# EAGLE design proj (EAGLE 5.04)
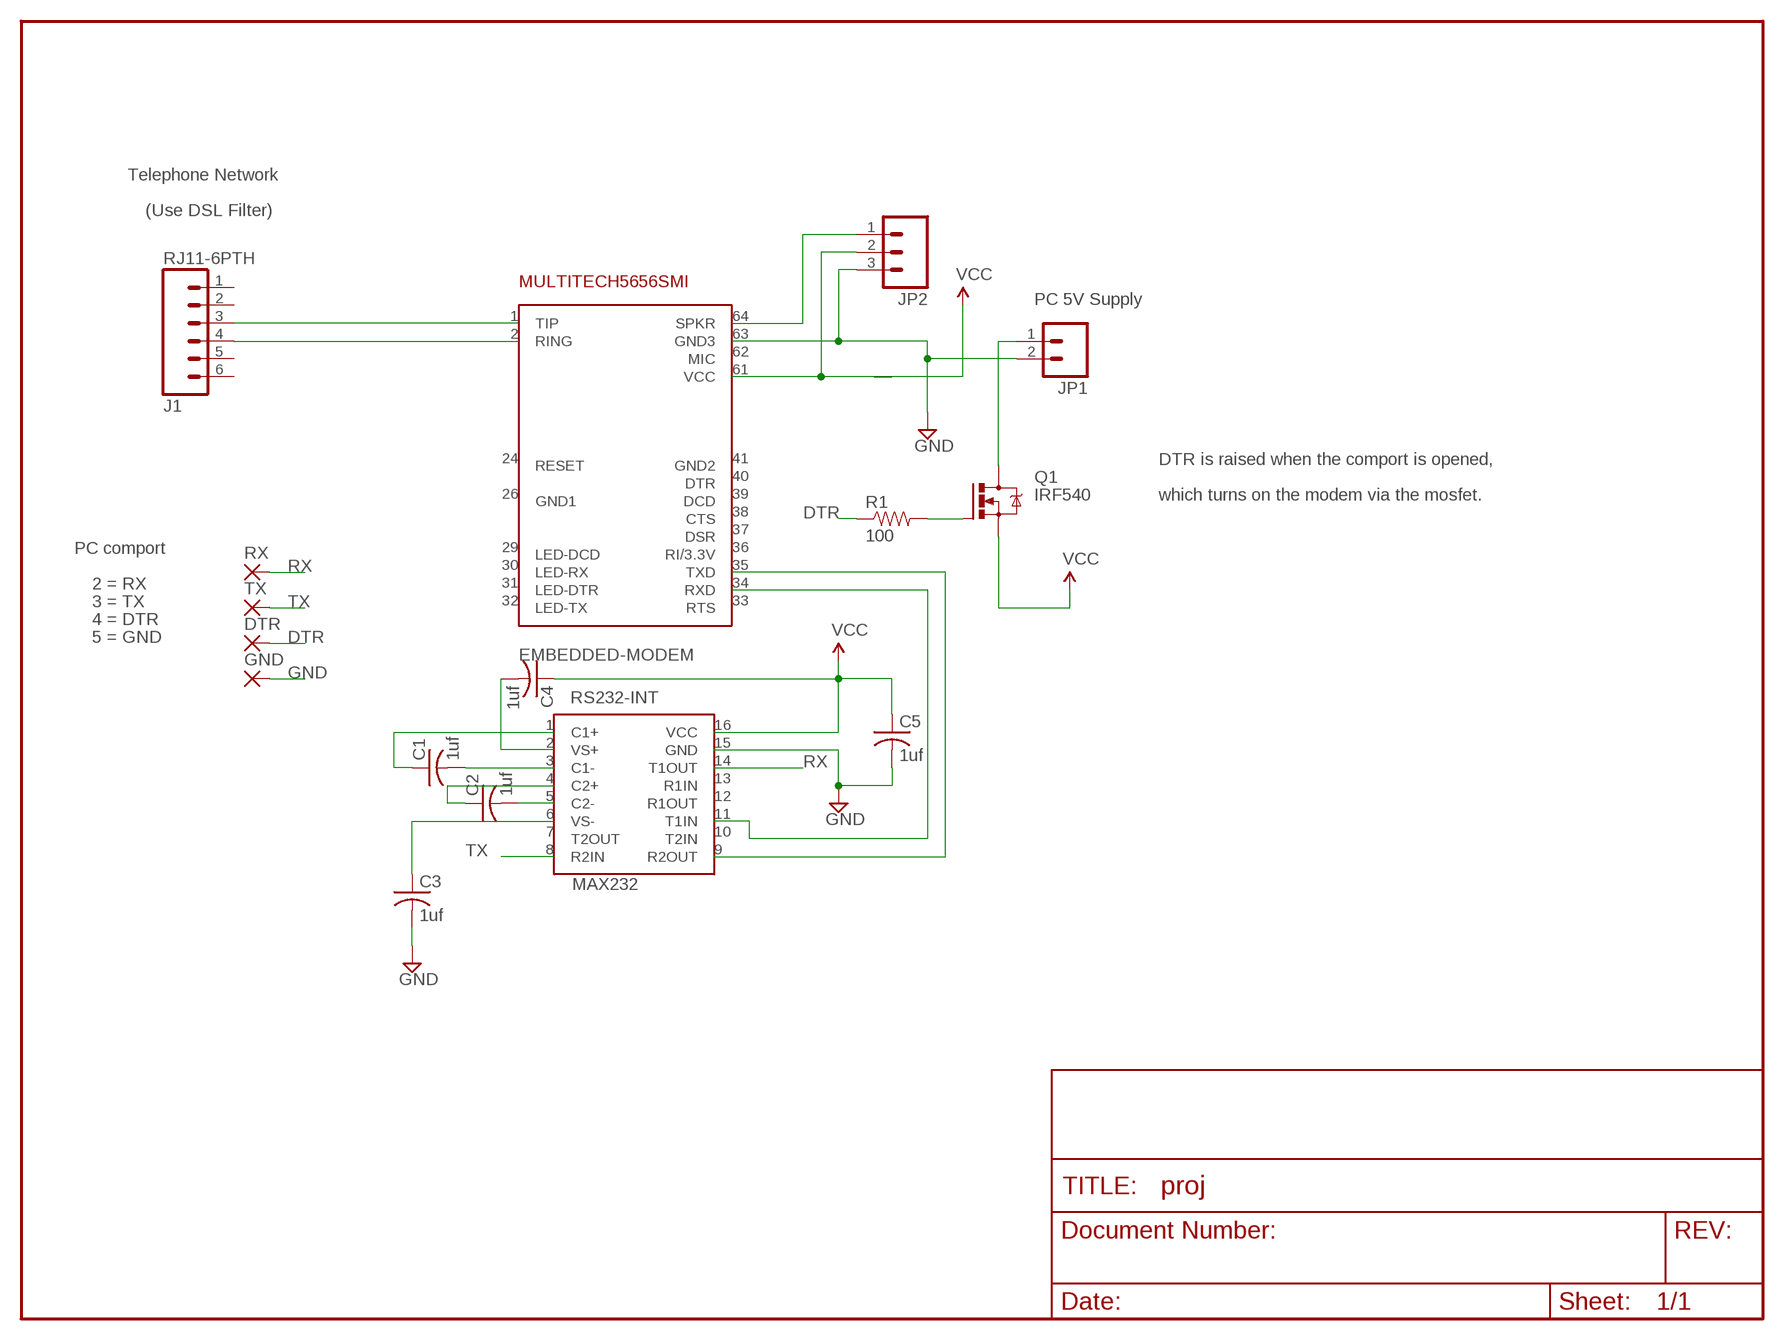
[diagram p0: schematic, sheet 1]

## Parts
C1  1uf  C-US050-024X044  [C050-024X044]
C2  1uf  C-US050-024X044  [C050-024X044]
C3  1uf  C-US050-024X044  [C050-024X044]
C4  1uf  C-US050-024X044  [C050-024X044]
C5  1uf  C-US050-024X044  [C050-024X044]
DTR  2,54/0,8  [2,54/0,8]
EMBEDDED-MODEM  MULTITECH5656SMI  [MULTITECH5656SMI]
GND  2,54/0,8  [2,54/0,8]
J1  RJ11-6PTH  [RJ11-6]
JP1  M02LOCK_LONGPADS  [1X02_LOCK_LONGPADS]
JP2  M03LOCK_LONGPADS  [1X03_LOCK_LONGPADS]
Q1  IRF540  [TO220BV]
R1  100  RESISTORPTH1  [AXIAL-0.3]
RS232-INT  MAX232  [DIL16-3]
RX  2,54/0,8  [2,54/0,8]
TX  2,54/0,8  [2,54/0,8]

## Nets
DTR: DTR.1(P) R1.P$1
GND: C3.2 C5.2 EMBEDDED-MODEM.63(GND3) GND.1(P) JP1.2 JP2.3 RS232-INT.15(GND)
N$2: Q1.G R1.P$2
N$3: JP1.1 Q1.D
N$4: EMBEDDED-MODEM.35(TXD) RS232-INT.9(R2OUT)
N$5: EMBEDDED-MODEM.34(RXD) RS232-INT.11(T1IN)
N$6: C1.2 RS232-INT.3(C1-)
N$7: C1.1 RS232-INT.1(C1+)
N$8: C2.2 RS232-INT.5(C2-)
N$9: C2.1 RS232-INT.4(C2+)
N$10: C3.1 RS232-INT.6(VS-)
N$11: C4.2 RS232-INT.2(VS+)
N$13: EMBEDDED-MODEM.64(SPKR) JP2.1
RING: EMBEDDED-MODEM.2(RING) J1.4
RX: RS232-INT.14(T1OUT) RX.1(P)
TIP: EMBEDDED-MODEM.1(TIP) J1.3
TX: RS232-INT.8(R2IN) TX.1(P)
VCC: C4.1 C5.1 EMBEDDED-MODEM.61(VCC) JP2.2 Q1.S RS232-INT.16(VCC)
Unconnected: EMBEDDED-MODEM.24(RESET) EMBEDDED-MODEM.26(GND1) EMBEDDED-MODEM.29(LED-DCD) EMBEDDED-MODEM.30(LED-RX) EMBEDDED-MODEM.31(LED-DTR) EMBEDDED-MODEM.32(LED-TX) EMBEDDED-MODEM.33(RTS) EMBEDDED-MODEM.36(RI/3.3V) EMBEDDED-MODEM.37(DSR) EMBEDDED-MODEM.38(CTS) EMBEDDED-MODEM.39(DCD) EMBEDDED-MODEM.40(DTR) EMBEDDED-MODEM.41(GND2) EMBEDDED-MODEM.62(MIC) J1.1 J1.2 J1.5 J1.6 RS232-INT.7(T2OUT) RS232-INT.10(T2IN) RS232-INT.12(R1OUT) RS232-INT.13(R1IN)

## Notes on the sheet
- Telephone Network
- (Use DSL Filter)
- PC 5V Supply
- DTR is raised when the comport is opened,
- which turns on the modem via the mosfet.
- PC comport
- 2 = RX
- 3 = TX
- 4 = DTR
- 5 = GND

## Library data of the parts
C1-C5 = rcl:C-US: CAPACITOR, American symbol
DTR GND RX TX = wirepad:2,54/0,8: THROUGH-HOLE PAD
EMBEDDED-MODEM = trl:MULTITECH5656SMI
J1 = SparkFun:RJ11-6: RJ11 Jack Simple 6 pin RJ11 jack. Commonly found on CAT3 devices and Microchip programmers. SKU: PRT-00132
JP1 = SparkFun:M02: Header 2
JP2 = SparkFun:M03: Header 3 Standard 3-pin 0.1" header. Use with straight break away headers (SKU : PRT-00116), right angle break away headers (PRT-00553), swiss pins (PRT-00743), machine pins (PRT-00117), and female headers (PRT-00115). Molex polarized connector foot print use with SKU : PRT-08232 with associated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
Q1 = transistor-power:IRF540: HEXFET Power MOSFET
R1 = SparkFun:RESISTOR: Resistor
RS232-INT = trl:MAX232

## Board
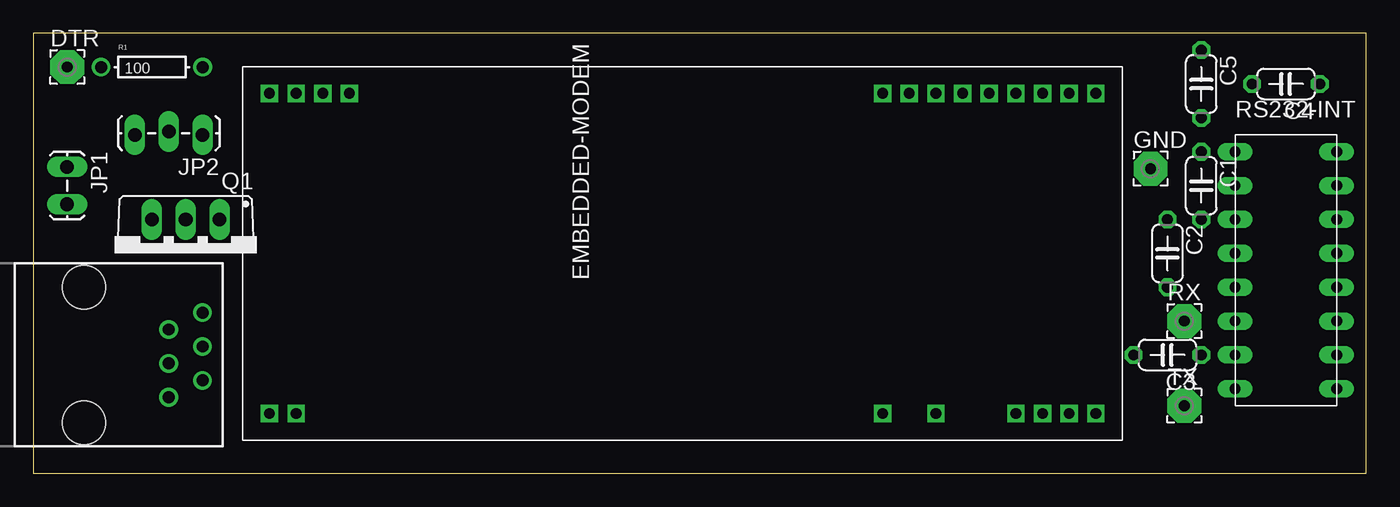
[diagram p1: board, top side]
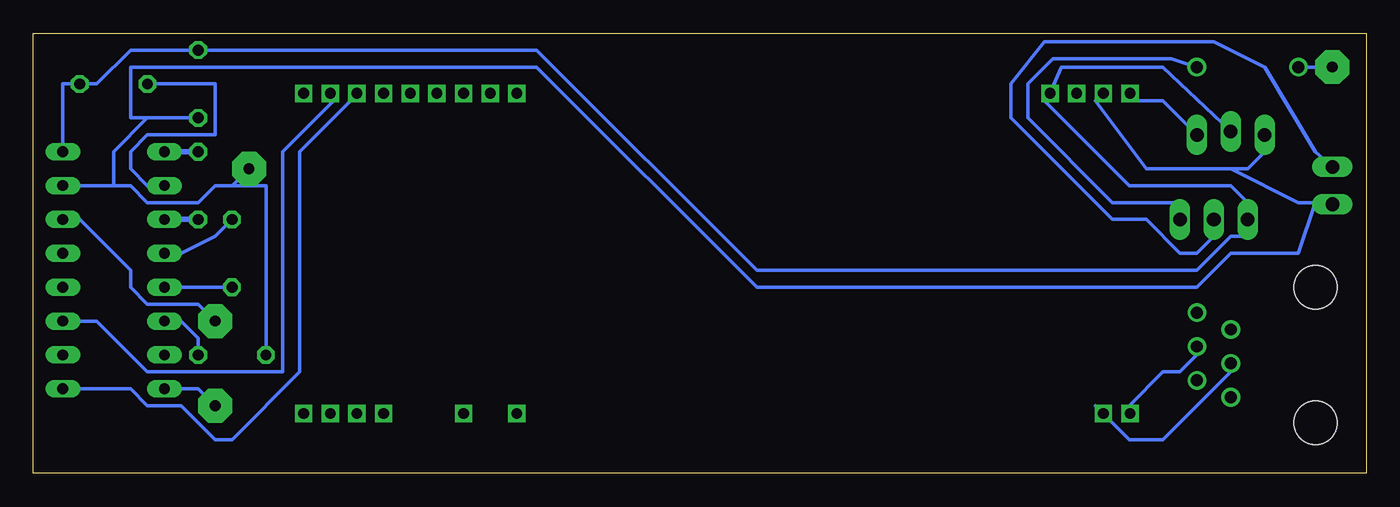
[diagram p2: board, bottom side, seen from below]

Size 100 x 33.01 mm. Coordinates in mm from the lower left corner, seen from the top.
Outline: 0,0 100,0 100,33.01 0,33.01 0,0
Copper layers (1*16): Top 0.035mm / dielectric 1.5mm / Bottom 0.035mm
Design rules "default": minimum track width 10mil, minimum drill 24mil, track to track 8mil, track to pad 8mil, pad to pad 8mil, via to via 8mil, smd to smd 8mil, copper to edge 40mil, drill to drill 8mil, minimum pad ring 10mil, minimum via ring 8mil, stop-mask expansion 4mil, vias tented up to drill 0mil, thermal gap 10mil

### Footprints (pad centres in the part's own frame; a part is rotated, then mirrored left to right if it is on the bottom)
C050-024X044 = drill 0.813 octagon: 1 -2.54,0; 2 2.54,0
2,54/0,8 = drill 0.813 pad 2.54 octagon: 1 0,0
MULTITECH5656SMI = drill 0.8 square: 1 -12,28; 2 -12,26; 24 -12,-18; 26 -12,-22; 29 -12,-28; 30 -12,-30; 31 -12,-32; 32 -12,-34; 33 12,-34; 34 12,-32; 35 12,-30; 36 12,-28; 37 12,-26; 38 12,-24; 39 12,-22; 40 12,-20; 41 12,-18; 61 12,22; 62 12,24; 63 12,26; 64 12,28
RJ11-6 = drill 0.889 round: 1 1.905,8.89; 2 3.175,6.35; 3 4.445,8.89; 4 5.715,6.35; 5 6.985,8.89; 6 8.255,6.35 | hole 3.251: 0,0; 10.16,0
1X02_LOCK_LONGPADS = drill 1.016 long: 1 -0.127,0; 2 2.667,0
1X03_LOCK_LONGPADS = drill 1.016 long: 1 0,0; 2 2.54,-0.254; 3 5.08,0
TO220BV = drill 1.016 long: D 0,-2.54; G -2.54,-2.54; S 2.54,-2.54
AXIAL-0.3 = drill 0.9 round: P$1 -3.81,0; P$2 3.81,0
DIL16-3 = drill 0.8 long: 1 -3.81,8.89; 2 -3.81,6.35; 3 -3.81,3.81; 4 -3.81,1.27; 5 -3.81,-1.27; 6 -3.81,-3.81; 7 -3.81,-6.35; 8 -3.81,-8.89; 9 3.81,-8.89; 10 3.81,-6.35; 11 3.81,-3.81; 12 3.81,-1.27; 13 3.81,1.27; 14 3.81,3.81; 15 3.81,6.35; 16 3.81,8.89

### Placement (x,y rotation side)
C1  87.63,21.59 270 top
C2  85.09,16.51 270 top
C3  85.09,8.89 180 top
C4  93.98,29.21 180 top
C5  87.63,29.21 270 top
DTR  2.54,30.48 0 top
EMBEDDED-MODEM  45.72,16.51 90 top
GND  83.82,22.86 0 top
J1  3.81,13.97 270 top
JP1  2.54,22.86 270 top
JP2  12.7,25.4 180 top
Q1  11.43,16.51 180 top
R1  8.89,30.48 0 top
RS232-INT  93.98,15.24 0 top
RX  86.36,11.43 0 top
TX  86.36,5.08 0 top

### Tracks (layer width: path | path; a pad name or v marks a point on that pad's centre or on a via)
DTR
  Bottom 0.254: DTR.1 R1.P$1
GND
  Bottom 0.254: 10.16,22.86 16.51,22.86 20.32,27.94 EMBEDDED-MODEM.63 | 10.16,22.86 5.08,20.32 3.81,20.32 | 3.81,20.32 JP1.2 3.81,20.32 | 85.09,21.59 GND.1 | 85.09,21.59 86.36,21.59 87.63,20.32 91.44,20.32 92.71,21.59 93.98,21.59 | 93.98,21.59 96.52,21.59 RS232-INT.15 | C3.2 82.55,21.59 85.09,21.59 | 91.44,26.67 C5.2 | 91.44,26.67 93.98,24.13 93.98,21.59 | 3.81,20.32 5.08,16.51 10.16,16.51 12.7,13.97 45.72,13.97 62.23,30.48 92.71,30.48 92.71,26.67 91.44,26.67 | 10.16,22.86 8.89,22.86 7.62,24.13 JP2.3
N$2
  Bottom 0.254: R1.P$2 14.61,31.11 23.5,31.11 25.4,29.21 25.4,26.67 19.05,20.32 13.97,20.32 Q1.G
N$3
  Bottom 0.254: Q1.D 11.43,17.78 12.7,16.51 13.97,16.51 16.51,19.05 19.05,19.05 26.67,26.67 26.67,29.21 24.13,32.38 11.43,32.38 7.62,30.48 3.81,24.13 JP1.1
N$4
  Bottom 0.254: EMBEDDED-MODEM.35 76.2,27.94 80.01,24.13 80.01,7.62 85.09,2.54 86.36,2.54 88.9,5.08 91.44,5.08 92.71,6.35 96.52,6.35 RS232-INT.9
N$5
  Bottom 0.254: EMBEDDED-MODEM.34 77.47,27.94 81.28,24.13 81.28,7.62 91.44,7.62 95.25,11.43 96.52,11.43 RS232-INT.11
N$6
  Bottom 0.406: C1.2 RS232-INT.3
N$7
  Bottom 0.254: RS232-INT.1 88.9,24.13
  Bottom 0.406: C1.1 RS232-INT.1
N$8
  Bottom 0.254: C2.2 88.9,13.97 RS232-INT.5
N$9
  Bottom 0.254: C2.1 86.36,17.78 88.9,16.51 RS232-INT.4
N$10
  Bottom 0.254: C3.1 87.63,10.16 88.9,11.43 RS232-INT.6
N$11
  Bottom 0.254: C4.2 86.36,29.21 86.36,25.4 91.44,25.4 92.71,24.13 92.71,22.86 91.44,21.59 RS232-INT.2
N$13
  Bottom 0.254: EMBEDDED-MODEM.64 17.78,27.94 15.24,27.94 13.97,26.67 JP2.1
RING
  Bottom 0.254: EMBEDDED-MODEM.2 20.32,5.08 17.78,2.54 15.24,2.54 10.16,7.62 J1.4
RX
  Bottom 0.254: RX.1 87.63,12.7 91.44,12.7 92.71,13.97 92.71,15.24 96.52,19.05 RS232-INT.14
TIP
  Bottom 0.254: EMBEDDED-MODEM.1 17.78,5.08 15.24,7.62 13.97,7.62 12.7,8.89 J1.3
TX
  Bottom 0.254: TX.1 87.63,6.35 88.9,6.35 RS232-INT.8
VCC
  Bottom 0.254: RS232-INT.16 97.79,29.21 C4.1 95.25,29.21 92.71,31.75 C5.1 62.23,31.75 45.72,15.24 12.7,15.24 10.16,17.78 8.89,17.78 Q1.S 8.89,20.32 10.16,21.59 17.78,21.59 24.13,27.94 EMBEDDED-MODEM.61 22.86,30.48 15.24,30.48 JP2.2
